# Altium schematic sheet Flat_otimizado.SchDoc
size A4
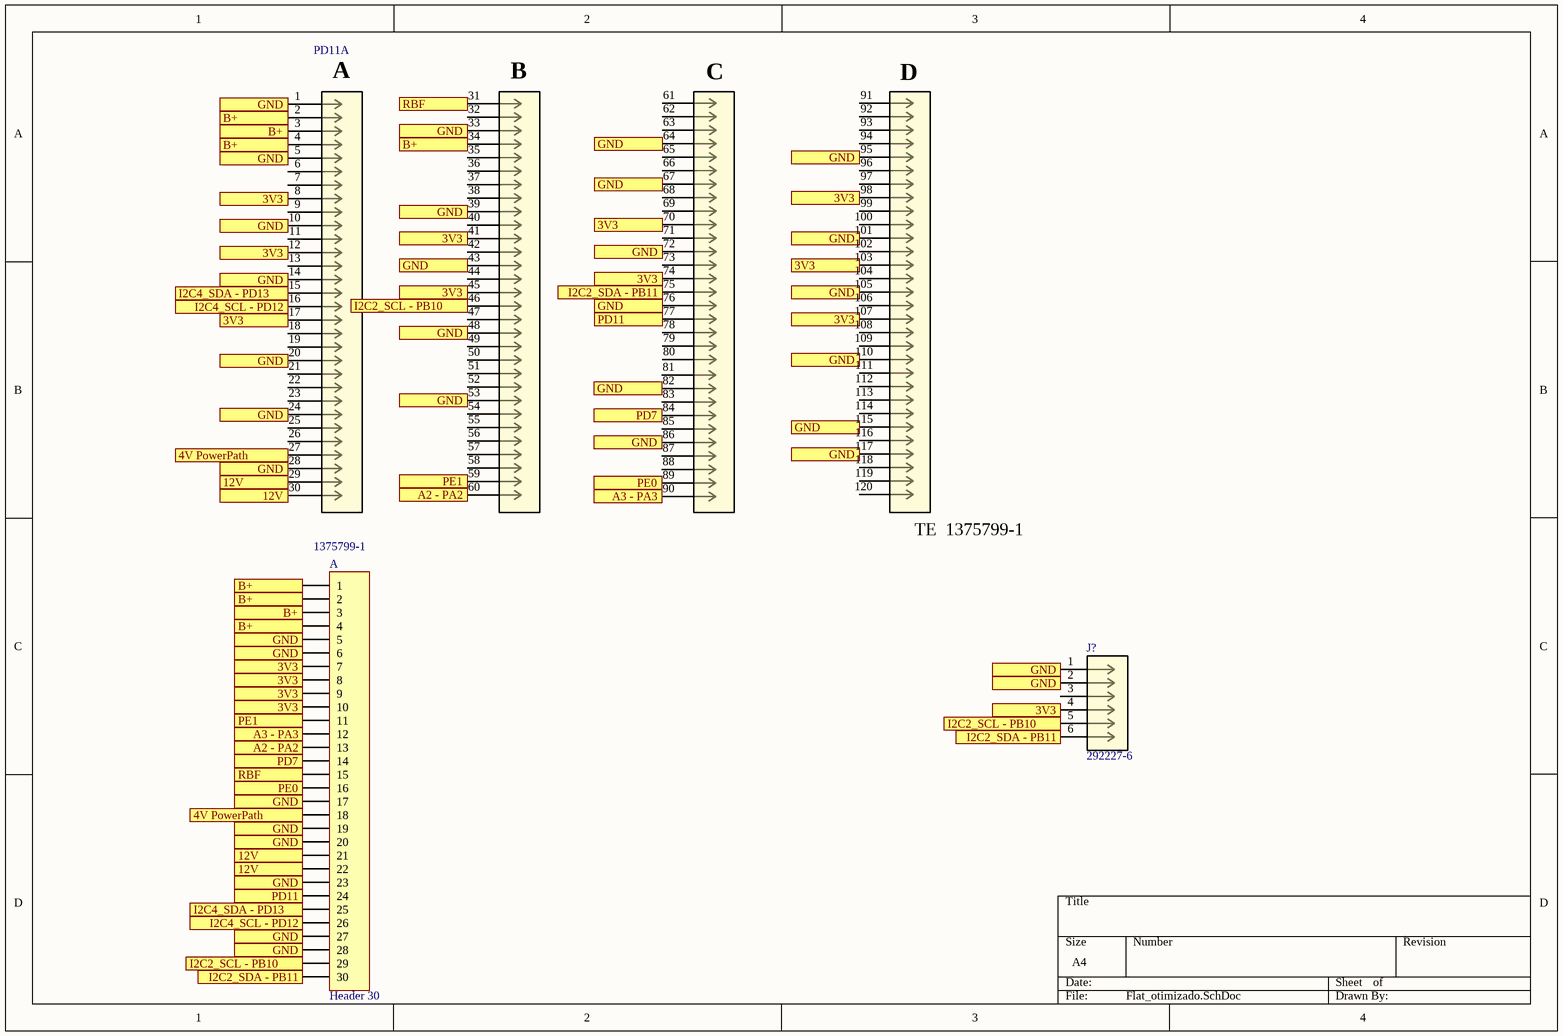
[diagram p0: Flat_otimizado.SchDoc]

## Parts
A  Header 30  [HDR1X30]
J?  292227-6  [CON6_1X6_DRH_HPI125_TYC]
PD11  1375799-1  [CONN_1375799-1_T]  (part A of 3)

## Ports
3V3, 4V PowerPath, 12V, A2 - PA2, A3 - PA3, B+, GND, I2C2_SCL - PB10, I2C2_SDA - PB11, I2C4_SCL - PD12, I2C4_SDA - PD13, PD7, PD11, PE0, PE1, RBF

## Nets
3V3: A.7 A.8 A.9 A.10 J?.4 PD11.8 PD11.12 PD11.17 PD11.41 PD11.45 PD11.70 PD11.74 PD11.98 PD11.103 PD11.107 ; port 3V3
4V PowerPath: A.18 PD11.27 ; port 4V PowerPath
12V: A.21 A.22 PD11.29 PD11.30 ; port 12V
A2 - PA2: A.13 PD11.60 ; port A2 - PA2
A3 - PA3: A.12 PD11.90 ; port A3 - PA3
B+: A.1 A.2 A.3 A.4 PD11.2 PD11.3 PD11.4 PD11.34 ; port B+
GND: A.5 A.6 A.17 A.19 A.20 A.23 A.27 A.28 J?.1 J?.2 PD11.1 PD11.5 PD11.10 PD11.14 PD11.20 PD11.24 PD11.28 PD11.33 PD11.39 PD11.43 PD11.48 PD11.53 PD11.64 PD11.67 PD11.72 PD11.76 PD11.82 PD11.86 PD11.95 PD11.101 PD11.105 PD11.110 PD11.115 PD11.117 ; port GND
I2C2_SCL - PB10: A.29 J?.5 PD11.46 ; port I2C2_SCL - PB10
I2C2_SDA - PB11: A.30 J?.6 PD11.75 ; port I2C2_SDA - PB11
I2C4_SCL - PD12: A.26 PD11.16 ; port I2C4_SCL - PD12
I2C4_SDA - PD13: A.25 PD11.15 ; port I2C4_SDA - PD13
PD7: A.14 PD11.84 ; port PD7
PD11: A.24 PD11.77 ; port PD11
PE0: A.16 PD11.89 ; port PE0
PE1: A.11 PD11.59 ; port PE1
RBF: A.15 PD11.31 ; port RBF

Not connected (* = marked no-connect by the designer): J? 3; PD11 6 7 9 11 13 18 19 21 22 23 25 26 32 35 36 37 38 40 42 44 47 49 50 51 52 54 55 56 57 58 61(21) 62(22) 63(23) 65(25) 66 68 69 71 73 78(38) 79 80 81 83 85 87 88 91 92 93 94 96 97 99 100 102 104 106 108 109 111 112 113 114 116 118 119 120

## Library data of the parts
A = Header 30: Header, 30-Pin
J? = 292227-6: No Description Available; Vendor: TE Connectivity; Built_By: EMA_UL_Team; SourceLibrary: Tyco_2012-01-01_HPI_125SRA
PD11 = 1375799-1: No Description Available; Vendor: TE Connectivity; Built_By: EMA_UL_Team; SourceLibrary: Tyco_2012-1-03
